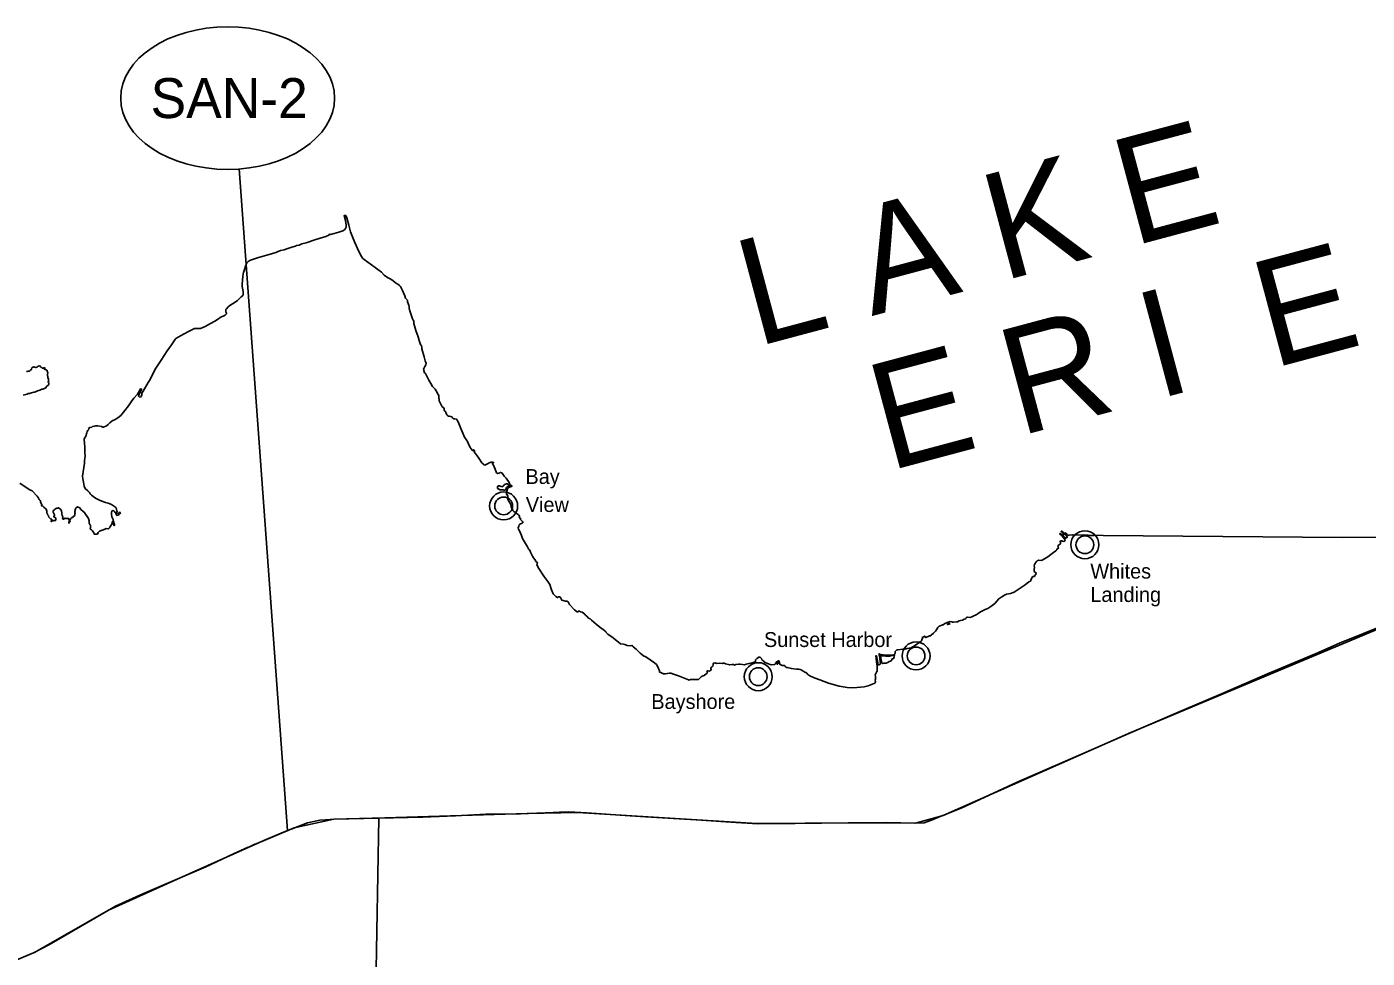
# Model space of a CAD drawing. Extents: x 0 to 798, y 0 to 440.
# Drawn here: x 446.4 to 540.4, y 256.2 to 321.5 of the extents above; entities that cross this region are included whole.
import ezdxf

# ---------------------------------------------------------------- set-up
doc = ezdxf.new("R2010")
doc.units = 0
for name, color, linetype in [('DV_X_Corp_Line', 7, 'Continuous'), ('GM_X_County', 7, 'Continuous'), ('GM_X_State_Route', 7, 'Continuous'), ('GM_X_US_Route', 7, 'Continuous'), ('RW_X_Esmt_U', 7, 'Continuous'), ('SH_Data', 7, 'Continuous'), ('SH_Text', 7, 'Continuous')]:
    doc.layers.add(name, color=color, linetype=linetype)

msp = doc.modelspace()

# ---------------------------------------------------------------- linework, layer by layer
at = {"layer": 'DV_X_Corp_Line'}
for centre, radius in [((479.809, 287.947), 0.982), ((479.809, 287.947), 0.623), ((520.571, 285.224), 0.982), ((520.571, 285.224), 0.623), ((508.733, 277.427), 0.982), ((508.733, 277.427), 0.623), ((497.666, 275.97), 0.982), ((497.666, 275.97), 0.623)]:
    msp.add_circle(centre, radius, dxfattribs=at)
at = {"layer": 'GM_X_County'}
for points in [[(445.874, 289.536), (446.384, 289.193), (446.572, 289.072), (446.735, 289), (447.1, 288.642), (447.177, 288.537), (447.234, 288.405), (447.28, 288.354), (447.306, 288.325), (447.345, 288.243), (447.322, 288.215), (447.365, 288.14), (447.425, 288.019), (447.396, 287.98), (447.409, 287.952), (447.497, 287.936), (447.569, 287.867), (447.718, 287.715), (447.767, 287.584), (447.777, 287.465), (447.772, 287.429), (447.816, 287.388), (447.847, 287.305), (447.891, 287.251), (447.919, 287.161), (448.063, 287.027), (448.123, 287.009), (448.125, 286.973), (448.097, 286.917), (448.079, 286.868), (448.084, 286.837), (448.112, 286.875), (448.189, 286.904), (448.22, 286.901), (448.262, 286.929), (448.316, 286.927), (448.354, 286.919), (448.388, 286.909), (448.38, 286.96), (448.411, 286.986), (448.406, 287.04), (448.408, 287.097), (448.38, 287.117), (448.339, 287.138), (448.295, 287.169), (448.262, 287.208), (448.264, 287.231), (448.28, 287.244), (448.316, 287.244), (448.326, 287.267), (448.316, 287.329), (448.285, 287.37), (448.256, 287.424), (448.226, 287.509), (448.223, 287.568), (448.244, 287.627), (448.287, 287.653), (448.305, 287.689), (448.372, 287.748), (448.475, 287.779), (448.514, 287.782), (448.547, 287.8), (448.586, 287.813), (448.671, 287.766), (448.751, 287.684), (448.792, 287.584), (448.833, 287.473), (448.82, 287.414), (448.815, 287.37), (448.841, 287.28), (448.885, 287.179), (448.893, 287.133), (448.875, 287.107), (448.877, 287.076), (448.89, 287.061), (448.898, 287.02), (448.916, 287.012), (448.952, 287.002), (448.983, 287.056), (449.034, 287.079), (449.096, 287.063), (449.122, 287.053), (449.178, 287.053), (449.305, 287.056), (449.32, 287.025), (449.33, 286.976), (449.346, 286.953), (449.354, 286.917), (449.343, 286.845), (449.323, 286.808), (449.305, 286.772), (449.307, 286.741), (449.338, 286.739), (449.346, 286.762), (449.346, 286.788), (449.372, 286.814), (449.392, 286.85), (449.413, 286.86), (449.402, 286.888), (449.382, 286.896), (449.382, 286.922), (449.384, 286.968), (449.387, 287.012), (449.446, 287.02), (449.462, 287.061), (449.469, 287.099), (449.524, 287.138), (449.572, 287.141), (449.59, 287.146), (449.611, 287.182), (449.655, 287.231), (449.681, 287.236), (449.712, 287.236), (449.719, 287.277), (449.737, 287.313), (449.742, 287.378), (449.771, 287.427), (449.748, 287.494), (449.742, 287.545), (449.771, 287.617), (449.76, 287.682), (449.79, 287.742), (449.812, 287.788), (449.831, 287.824), (449.923, 287.881), (449.969, 287.87), (450.083, 287.802), (450.151, 287.696), (450.297, 287.574), (450.43, 287.469), (450.465, 287.401), (450.555, 287.268), (450.685, 287.067), (450.731, 286.905), (450.736, 286.794), (450.75, 286.731), (450.785, 286.655), (450.834, 286.604), (450.828, 286.425), (450.823, 286.333), (450.904, 286.273), (450.967, 286.203), (451.062, 286.062), (451.094, 285.959), (451.322, 285.967), (451.376, 286.086), (451.474, 286.175), (451.644, 286.251), (451.753, 286.276), (451.837, 286.316), (451.932, 286.357), (452.105, 286.338), (452.162, 286.4), (452.192, 286.455), (452.238, 286.533), (452.292, 286.596), (452.333, 286.685), (452.352, 286.794), (452.376, 286.872), (452.42, 286.845), (452.444, 286.791), (452.447, 286.72), (452.447, 286.642), (452.468, 286.593), (452.479, 286.571), (452.498, 286.596), (452.536, 286.596), (452.517, 286.623), (452.517, 286.672), (452.504, 286.712), (452.479, 286.712), (452.468, 286.788), (452.447, 286.861), (452.42, 287), (452.341, 287.178), (452.319, 287.36), (452.317, 287.501), (452.352, 287.599), (452.417, 287.615), (452.485, 287.574), (452.561, 287.493), (452.604, 287.433), (452.647, 287.325), (452.707, 287.282), (452.818, 287.319), (452.883, 287.39), (452.927, 287.42), (452.935, 287.452), (452.902, 287.515), (452.853, 287.493), (452.815, 287.436), (452.745, 287.406), (452.699, 287.431), (452.669, 287.485), (452.683, 287.515), (452.71, 287.547), (452.688, 287.599), (452.656, 287.694), (452.639, 287.81), (452.515, 287.908), (452.455, 287.962), (452.317, 288.038), (452.075, 288.135), (451.883, 288.176), (451.636, 288.274), (451.474, 288.344), (451.178, 288.501), (451.005, 288.623), (450.915, 288.691), (450.823, 288.794), (450.755, 288.881), (450.652, 289.003), (450.473, 289.168), (450.389, 289.331), (450.335, 289.621), (450.308, 289.849), (450.278, 290.038), (450.365, 290.632), (450.424, 290.952), (450.424, 291.139), (450.435, 291.275), (450.452, 291.464), (450.441, 291.657), (450.427, 291.841), (450.43, 291.977), (450.449, 292.15), (450.419, 292.264), (450.419, 292.343), (450.405, 292.421), (450.392, 292.53), (450.397, 292.625), (450.422, 292.703), (450.481, 292.801), (450.525, 292.909), (450.544, 292.999), (450.579, 293.064), (450.595, 293.167), (450.652, 293.237), (450.709, 293.297), (450.704, 293.381), (450.782, 293.443), (450.929, 293.481), (450.983, 293.508), (451.094, 293.533), (451.208, 293.571), (451.343, 293.571), (451.609, 293.519), (451.701, 293.481), (451.753, 293.479), (451.959, 293.573), (452.065, 293.647), (452.184, 293.785), (452.36, 293.912), (452.555, 294.007), (452.745, 294.116), (452.959, 294.295), (453.249, 294.642), (453.49, 294.967), (453.691, 295.246), (453.867, 295.512), (454.141, 295.775), (454.263, 296.021), (454.301, 296.095), (454.325, 296.138), (454.38, 296.149), (454.413, 296.141), (454.404, 296.097), (454.336, 295.948), (454.222, 295.718), (454.198, 295.655), (454.247, 295.601), (454.331, 295.574), (454.404, 295.664), (454.426, 295.737), (454.442, 295.864), (454.534, 295.994), (454.881, 296.607), (455.009, 296.821), (455.095, 296.987), (455.413, 297.613), (455.784, 298.166), (456.21, 298.827), (456.508, 299.242), (456.741, 299.586), (456.825, 299.678), (457.147, 299.865), (457.4, 300.02), (457.747, 300.21), (457.947, 300.305), (458.123, 300.378), (458.321, 300.378), (458.56, 300.397), (458.882, 300.54), (459.24, 300.736), (459.544, 300.893), (459.807, 301.056), (459.918, 301.169), (460.064, 301.24), (460.143, 301.251), (460.273, 301.329), (460.365, 301.422), (460.371, 301.468), (460.327, 301.562), (460.325, 301.63), (460.338, 301.731), (460.384, 301.769), (460.479, 301.899), (460.615, 302.007), (460.989, 302.229), (461.143, 302.349), (461.317, 302.514), (461.409, 302.603), (461.501, 302.674), (461.534, 302.715), (461.539, 302.978), (461.479, 303.341), (461.479, 303.503), (461.517, 304.046), (461.545, 304.23), (461.577, 304.317), (461.637, 304.534), (461.707, 304.759), (461.794, 304.994), (461.9, 305.095), (462.065, 305.171), (462.61, 305.379), (463.377, 305.58), (463.824, 305.729), (464.163, 305.87), (464.415, 305.913), (464.616, 305.984), (464.958, 306.092), (465.207, 306.168), (465.291, 306.209), (465.478, 306.244), (465.668, 306.331), (465.95, 306.401), (466.557, 306.602), (466.95, 306.729), (467.343, 306.849), (467.552, 306.941), (467.563, 306.971), (467.62, 306.995), (467.668, 306.976), (467.915, 307.055), (468.249, 307.152), (468.528, 307.239), (468.639, 307.31), (468.728, 307.407), (468.772, 307.489), (468.769, 307.646), (468.718, 307.96), (468.62, 308.31), (468.742, 308.318), (468.812, 308.161), (468.943, 307.638), (469.081, 307.169), (469.352, 306.469), (469.458, 306.212), (469.626, 305.829), (469.837, 305.431), (469.905, 305.328), (470.024, 305.225), (470.797, 304.669), (470.989, 304.523), (471.236, 304.328), (471.431, 304.135), (471.672, 303.959), (471.86, 303.864), (472.036, 303.747), (472.231, 303.601), (472.38, 303.49), (472.51, 303.4), (472.57, 303.341), (472.708, 303.048), (472.787, 302.885), (472.871, 302.669), (472.93, 302.519), (472.974, 302.471), (473.031, 302.427), (473.063, 302.384), (473.071, 302.338), (473.058, 302.265), (473.15, 302.031), (473.188, 301.899), (473.188, 301.793), (473.25, 301.554), (473.426, 301.069), (473.459, 300.969), (473.508, 300.893), (473.51, 300.831), (473.51, 300.744), (473.654, 300.253), (473.811, 299.795), (473.887, 299.537), (473.985, 299.269), (474.053, 299.169), (474.08, 299.085), (474.072, 299.036), (474.072, 298.971), (474.232, 298.412), (474.313, 298.117), (474.373, 297.935), (474.362, 297.84), (474.291, 297.729), (474.196, 297.542), (474.261, 297.287), (474.321, 297.233), (474.557, 296.764), (474.695, 296.536), (474.828, 296.311), (474.996, 296.124), (475.148, 295.902), (475.164, 295.824), (475.218, 295.756), (475.262, 295.68), (475.262, 295.577), (475.256, 295.487), (475.278, 295.43), (475.281, 295.311), (475.338, 295.222), (475.495, 294.896), (475.609, 294.815), (475.647, 294.753), (475.644, 294.652), (475.685, 294.598), (475.75, 294.544), (475.763, 294.49), (475.836, 294.341), (475.891, 294.262), (475.931, 294.235), (475.956, 294.23), (475.999, 294.238), (476.097, 294.216), (476.17, 294.189), (476.243, 294.102), (476.314, 294.064), (476.376, 294.064), (476.514, 294.024), (476.625, 293.855), (476.804, 293.367), (476.956, 293.039), (477.07, 292.771), (477.181, 292.608), (477.295, 292.424), (477.346, 292.267), (477.487, 292.026), (477.506, 291.969), (477.615, 291.841), (477.666, 291.83), (477.685, 291.849), (477.685, 291.874), (477.696, 291.893), (477.72, 291.876), (477.764, 291.83), (477.764, 291.765), (477.742, 291.741), (477.962, 291.451), (478.078, 291.288), (478.287, 290.979), (478.442, 290.817), (478.498, 290.814), (478.729, 290.914), (478.802, 290.963), (478.938, 291.017), (479.008, 291.02), (479.103, 290.998), (479.092, 290.979), (479.005, 290.903), (479.081, 290.849), (479.217, 290.516), (479.314, 290.269), (479.382, 290.209), (479.472, 290.239), (479.596, 290.293), (479.659, 290.269), (479.713, 290.255), (479.854, 290.044), (479.976, 289.887), (480.19, 289.578), (480.204, 289.542), (480.233, 289.51), (480.244, 289.469), (480.196, 289.445), (480.122, 289.453), (480.06, 289.488), (480, 289.488), (479.881, 289.453), (479.84, 289.404), (479.797, 289.344), (479.724, 289.298), (479.672, 289.296), (479.52, 289.347), (479.472, 289.355), (479.431, 289.347), (479.385, 289.296), (479.371, 289.225), (479.382, 289.176), (479.439, 289.136), (479.542, 289.073), (479.702, 289.073), (479.781, 289.073), (479.846, 289.046), (479.884, 289.041), (479.96, 289.098), (480.017, 289.236), (480.106, 289.307), (480.217, 289.353), (480.301, 289.369), (480.38, 289.374), (480.388, 289.35), (480.372, 289.307), (480.288, 289.293), (480.163, 289.236), (480.071, 289.144), (480.027, 288.97), (479.995, 288.889), (480.014, 288.783), (480.044, 288.713), (480.098, 288.718), (480.074, 288.678), (480.103, 288.602), (480.114, 288.477), (480.111, 288.398), (480.233, 288.163), (480.309, 288.013), (480.342, 287.889), (480.456, 287.626), (480.545, 287.523), (480.608, 287.498), (480.686, 287.441), (480.822, 287.352), (480.873, 287.29), (480.917, 287.233), (480.911, 287.173), (480.9, 287.141), (480.922, 287.111), (480.971, 287.094), (481.001, 287.073), (481.001, 286.997), (481.044, 286.937), (481.131, 286.85), (481.166, 286.807), (481.158, 286.775), (481.104, 286.745), (480.955, 286.669), (480.9, 286.612), (480.868, 286.517), (480.835, 286.411), (480.849, 286.322), (480.93, 286.189), (481.06, 285.877), (481.131, 285.658), (481.48, 285.067), (481.578, 284.899), (481.646, 284.836), (481.673, 284.766), (481.695, 284.709), (481.757, 284.56), (481.825, 284.427), (481.895, 284.302), (481.99, 284.18), (482.077, 284.077), (482.09, 284.031), (482.126, 284.004), (482.164, 283.988), (482.172, 283.925), (482.134, 283.844), (482.234, 283.625), (482.624, 283.02), (482.912, 282.64), (483.047, 282.443), (483.168, 282.059), (483.283, 281.781), (483.469, 281.599), (483.592, 281.523), (483.668, 281.563), (483.755, 281.571), (483.767, 281.543), (483.814, 281.468), (483.89, 281.337), (484.144, 281.257), (484.251, 281.277), (484.334, 281.214), (484.438, 281.031), (484.779, 280.65), (484.981, 280.499), (485.04, 280.559), (485.119, 280.559), (485.207, 280.514), (485.305, 280.493), (485.499, 280.36), (485.554, 280.288), (485.635, 280.206), (485.764, 280.077), (485.882, 280.018), (485.963, 279.944), (486.291, 279.654), (486.676, 279.348), (486.757, 279.31), (486.925, 279.158), (487, 279.097), (487.004, 279.059), (487.117, 278.95), (487.481, 278.69), (487.651, 278.557), (487.866, 278.387), (488.016, 278.283), (488.226, 278.24), (488.312, 278.219), (488.466, 278.147), (488.676, 278.131), (488.796, 278.147), (488.855, 278.131), (488.884, 278.086), (488.896, 278.072), (489.097, 277.909), (489.391, 277.626), (489.627, 277.443), (489.772, 277.355), (490.082, 277.149), (490.396, 276.936), (490.518, 276.823), (490.634, 276.665), (490.735, 276.389), (490.738, 276.291), (490.831, 276.262), (491.025, 276.167), (491.152, 276.162), (491.292, 276.196), (491.432, 276.212), (491.534, 276.217), (491.729, 276.156), (491.935, 276.072), (492.061, 276.033), (492.19, 275.986), (492.414, 275.884), (492.763, 275.755), (492.831, 275.735), (492.86, 275.76), (492.908, 275.791), (492.971, 275.782), (493.01, 275.771), (493.154, 275.771), (493.234, 275.764), (493.388, 275.766), (493.469, 275.782), (493.569, 275.861), (493.666, 275.972), (493.734, 276.013), (493.883, 276.065), (494.019, 276.167), (494.069, 276.203), (494.096, 276.248), (494.089, 276.285), (494.063, 276.313), (494.096, 276.377), (494.139, 276.386), (494.267, 276.356), (494.324, 276.411), (494.361, 276.466), (494.347, 276.563), (494.376, 276.649), (494.422, 276.676), (494.471, 276.717), (494.494, 276.792), (494.514, 276.9), (494.544, 276.927), (494.634, 276.939), (494.738, 276.907), (494.962, 276.914), (495.153, 276.9), (495.202, 276.916), (495.279, 276.911), (495.374, 276.873), (495.571, 276.83), (495.666, 276.792), (495.822, 276.825), (495.922, 276.816), (495.997, 276.789), (496.094, 276.814), (496.279, 276.844), (496.402, 276.848), (496.571, 276.83), (496.691, 276.81), (496.811, 276.853), (497.008, 276.891), (497.164, 276.923), (497.381, 277), (497.463, 277.022), (497.461, 277.068), (497.463, 277.151), (497.508, 277.194), (497.558, 277.235), (497.651, 277.298), (497.68, 277.337), (497.732, 277.346), (497.807, 277.328), (497.893, 277.237), (497.927, 277.158), (497.99, 277.115), (498.02, 277.102), (498.042, 277.072), (498.058, 277.029), (498.151, 276.973), (498.323, 276.891), (498.563, 276.805), (498.8, 276.828), (498.873, 276.88), (498.913, 276.952), (498.931, 277.009), (498.945, 277.018), (498.965, 277.004), (498.961, 276.952), (498.961, 276.868), (498.993, 276.841), (499.026, 276.841), (499.081, 276.923), (499.083, 276.991), (499.076, 277.022), (499.038, 277.031), (499.04, 277.072), (499.076, 277.088), (499.115, 277.081), (499.149, 276.975), (499.16, 276.887), (499.198, 276.828), (499.334, 276.764), (499.486, 276.746), (499.547, 276.699), (499.565, 276.653), (499.622, 276.624), (499.703, 276.624), (499.99, 276.536), (500.16, 276.524), (500.348, 276.502), (500.513, 276.497), (500.595, 276.47), (500.672, 276.452), (500.816, 276.353), (500.968, 276.276), (501.025, 276.264), (501.068, 276.224), (501.131, 276.126), (501.28, 276.04), (501.534, 275.923), (501.647, 275.867), (501.979, 275.742), (502.602, 275.511), (503.346, 275.316), (503.898, 275.214), (504.186, 275.194), (504.584, 275.201), (505.082, 275.253), (505.38, 275.323), (505.733, 275.472), (505.835, 275.524), (505.869, 275.57), (505.887, 275.631), (505.874, 275.717), (505.858, 275.751), (505.881, 275.755), (505.892, 275.769), (505.894, 275.882), (505.876, 276.011), (505.869, 276.09), (505.926, 276.233), (505.98, 276.325), (506.005, 276.353), (506.012, 276.481), (506.005, 276.543), (505.994, 276.699), (505.964, 277.004), (505.937, 277.278), (505.908, 277.432), (505.957, 277.439), (506, 277.199), (506.048, 276.952), (506.05, 276.868), (506.071, 276.792), (506.154, 276.794), (506.188, 276.844), (506.231, 276.862), (506.172, 277.434), (506.136, 277.493), (506.136, 277.545), (506.168, 277.593), (506.193, 277.579), (506.227, 277.531), (506.62, 277.486), (507.125, 277.513), (507.168, 277.484), (507.078, 277.445), (506.881, 277.409), (506.607, 277.4), (506.365, 277.427), (506.249, 277.43), (506.256, 277.273), (506.274, 277.147), (506.29, 277.117), (506.317, 277.079), (506.322, 276.988), (506.31, 276.959), (506.374, 276.9), (506.417, 276.896), (506.449, 276.925), (506.55, 276.925), (506.641, 276.93), (506.747, 276.968), (506.847, 277.027), (506.944, 277.056), (507.016, 277.104), (507.046, 277.163), (507.039, 277.215), (507.1, 277.224), (507.184, 277.258), (507.155, 277.283), (507.182, 277.326), (507.204, 277.371), (507.188, 277.43), (507.225, 277.468), (507.211, 277.545), (507.256, 277.604), (507.274, 277.74), (507.336, 277.812), (507.392, 277.857), (507.446, 277.864), (507.804, 277.896), (507.96, 277.925), (507.958, 277.905), (508.114, 277.936), (508.247, 277.97), (508.288, 277.966), (508.306, 277.952), (508.612, 278.136), (509.094, 278.452), (509.132, 278.514), (509.137, 278.59), (509.193, 278.647), (509.2, 278.67), (509.168, 278.719), (509.336, 278.814), (509.386, 278.726), (509.407, 278.721), (509.675, 278.842), (509.69, 278.823), (509.826, 278.903), (509.965, 279.025), (510.089, 279.174), (510.171, 279.26), (510.25, 279.412), (510.354, 279.509), (510.415, 279.548), (510.528, 279.577), (510.589, 279.616), (510.637, 279.609), (510.759, 279.699), (510.872, 279.758), (510.954, 279.801), (510.967, 279.785), (510.979, 279.706), (510.927, 279.674), (510.936, 279.636), (510.967, 279.638), (511.105, 279.674), (511.085, 279.711), (511.058, 279.715), (511.028, 279.715), (511.006, 279.74), (511.008, 279.803), (511.117, 279.842), (511.234, 279.817), (511.282, 279.797), (511.35, 279.797), (511.569, 279.81), (511.637, 279.812), (511.766, 279.878), (511.852, 279.903), (511.995, 279.946), (512.097, 279.998), (512.232, 280.03), (512.257, 280.111), (512.332, 280.156), (512.526, 280.131), (512.633, 280.159), (512.791, 280.236), (512.936, 280.301), (513.079, 280.394), (513.249, 280.52), (513.384, 280.581), (513.585, 280.686), (513.76, 280.758), (513.905, 280.847), (514.066, 280.952), (514.256, 281.103), (514.398, 281.274), (514.531, 281.439), (514.758, 281.577), (514.932, 281.686), (515.072, 281.763), (515.217, 281.779), (515.357, 281.795), (515.611, 281.896), (515.821, 282.03), (516.17, 282.263), (516.325, 282.369), (516.496, 282.509), (516.631, 282.615), (516.753, 282.679), (516.785, 282.711), (516.781, 282.774), (516.903, 282.969), (516.95, 283.017), (516.998, 282.994), (517.029, 283.005), (517.113, 283.132), (517.143, 283.139), (517.149, 283.254), (517.12, 283.259), (517.068, 283.308), (517.019, 283.377), (517.003, 283.483), (517.025, 283.553), (517.043, 283.591), (517.036, 283.661), (517.009, 283.745), (517.029, 283.842), (517.154, 284.033), (517.226, 284.103), (517.351, 284.134), (517.53, 284.13), (517.74, 284.229), (517.969, 284.386), (518.179, 284.539), (518.362, 284.682), (518.534, 284.8), (518.6, 284.874), (518.604, 284.917), (518.625, 284.933), (518.663, 284.933), (518.697, 284.972), (518.711, 285.008), (518.686, 285.112), (518.69, 285.168), (518.799, 285.245), (518.831, 285.261), (518.865, 285.291), (518.871, 285.334), (518.853, 285.383), (518.831, 285.44), (518.847, 285.476), (518.903, 285.488), (518.955, 285.501), (519.012, 285.483), (519.086, 285.454), (519.111, 285.454), (519.145, 285.475), (519.181, 285.557), (519.086, 285.685), (518.981, 285.82), (518.88, 285.91), (518.817, 285.957), (518.814, 285.989), (518.828, 286.016), (518.855, 286.016), (518.967, 285.93), (519.012, 285.924), (519.048, 285.903), (519.066, 285.883), (519.075, 285.825), (519.129, 285.766), (519.183, 285.697), (519.235, 285.676), (519.329, 285.755), (519.266, 285.881), (519.192, 285.953), (519.161, 285.964), (519.109, 285.969), (519.048, 286.018), (518.943, 286.126), (518.909, 286.142), (518.911, 286.169), (518.954, 286.178), (519.028, 286.124), (519.12, 286.043), (519.21, 286.056), (519.246, 286.032), (519.376, 285.863), (519.446, 285.901), (519.687, 285.912), (519.743, 285.901), (519.828, 285.901), (520.491, 285.917), (520.8, 285.896), (520.943, 285.883), (520.978, 285.878), (521.061, 285.868), (521.13, 285.865), (521.165, 285.867), (521.206, 285.875), (521.245, 285.889), (521.264, 285.897), (521.853, 285.883), (538.638, 285.734), (556.572, 285.782)], [(446.351, 297.383), (446.4, 297.373), (446.464, 297.398), (446.51, 297.398), (446.549, 297.398), (446.585, 297.424), (446.606, 297.432), (446.624, 297.465), (446.631, 297.491), (446.66, 297.506), (446.673, 297.483), (446.691, 297.532), (446.722, 297.625), (446.765, 297.666), (446.819, 297.687), (446.85, 297.687), (446.889, 297.707), (446.915, 297.684), (446.992, 297.653), (447.113, 297.697), (447.162, 297.741), (447.237, 297.764), (447.306, 297.749), (447.329, 297.71), (447.365, 297.661), (447.414, 297.658), (447.443, 297.622), (447.466, 297.599), (447.52, 297.604), (447.566, 297.62), (447.6, 297.648), (447.633, 297.609), (447.623, 297.571), (447.597, 297.543), (447.646, 297.514), (447.726, 297.499), (447.752, 297.481), (447.801, 297.455), (447.793, 297.396), (447.78, 297.38), (447.819, 297.347), (447.844, 297.331), (447.816, 297.13), (447.811, 297.071), (447.847, 297.015), (447.837, 296.924), (447.888, 296.852), (447.888, 296.747), (447.898, 296.664), (447.852, 296.631), (447.886, 296.603), (447.911, 296.564), (447.911, 296.476), (447.896, 296.435), (447.731, 296.296), (447.692, 296.234), (447.62, 296.18), (447.548, 296.157), (447.484, 296.139), (447.414, 296.131), (447.291, 296.056), (447.201, 296.044), (447.123, 296.01), (447.061, 295.992), (446.982, 295.943), (446.92, 295.933), (446.855, 295.93), (446.696, 295.879), (446.567, 295.835), (446.474, 295.84), (446.389, 295.784), (446.106, 295.719)]]:
    msp.add_lwpolyline(points, dxfattribs=at)
at = {"layer": 'GM_X_State_Route'}
msp.add_lwpolyline([(469.488, 195.343), (469.722, 206.488), (469.906, 206.741), (469.984, 206.905), (470.105, 213.119), (470.31, 219.731), (470.468, 230.182), (470.519, 233.299), (470.702, 246.178), (471.047, 266.057)], dxfattribs=at)
at = {"layer": 'GM_X_US_Route'}
for points in [[(516.739, 268.965), (516.74, 268.965), (520.277, 270.512), (523.664, 271.997), (525.17, 272.645), (527.506, 273.651), (530.157, 274.761), (533.373, 276.17), (536.78, 277.606), (538.433, 278.327), (546.836, 281.711), (565.775, 289.63)], [(483.768, 266.474), (484.374, 266.497), (485.653, 266.415), (487.981, 266.264), (489.764, 266.142), (493.309, 265.925), (496.098, 265.735), (497.664, 265.66), (500.246, 265.669), (503.973, 265.717), (506.672, 265.743), (508.643, 265.692), (509.3, 265.713), (509.816, 265.905), (510.254, 266.084), (511.885, 266.752), (515.818, 268.562), (516.739, 268.965)], [(467.383, 265.93), (467.906, 265.969), (471.047, 266.057), (474.147, 266.108), (476.434, 266.224), (477.73, 266.285), (478.555, 266.324), (480.998, 266.354), (483.28, 266.455), (483.729, 266.472), (483.768, 266.474)], [(462.453, 264.253), (463.308, 264.629), (464.48, 265.117), (466.045, 265.724), (466.928, 265.897), (467.322, 265.926), (467.383, 265.93)], [(461.979, 264.044), (462.367, 264.215), (462.453, 264.253)], [(444.366, 255.572), (444.489, 255.618), (446.841, 256.594), (447.964, 257.197), (452.579, 259.871), (454.511, 260.742), (458.933, 262.646), (460.862, 263.553), (461.896, 264.008), (461.979, 264.044)]]:
    msp.add_lwpolyline(points, dxfattribs=at)
at = {"layer": 'SH_Data'}
msp.add_line((461.27, 311.576), (464.657, 265.173), dxfattribs=at)
msp.add_ellipse((460.454, 316.547), major_axis=(7.5, 0), ratio=0.666667, dxfattribs=at)
at = {"layer": 'SH_Text'}
msp.add_lwpolyline([(446.901, 256.627), (452.098, 259.592), (456.653, 261.664), (462.561, 264.3), (465.11, 265.361), (467.906, 265.969), (471.469, 266.064), (481.455, 266.375), (485.005, 266.456), (491.844, 266.015), (497.558, 265.665), (504.325, 265.72), (508.682, 265.693), (510.644, 266.244), (523.798, 272.054), (556.954, 285.941)], dxfattribs=at)

# ---------------------------------------------------------------- texts
at = {"layer": 'DV_X_Corp_Line'}
for s, height, p in [('Bay', 1.0417, (481.339, 289.486)), ('View', 1.0417, (481.366, 287.522)), ('Whites', 1.0417, (520.956, 282.849)), ('Landing', 1.0417, (520.956, 281.21)), ('Sunset Harbor', 1.04167, (498.065, 278.053)), ('Bayshore', 1.0417, (490.167, 273.708))]:
    msp.add_text(s, height=height, rotation=0.00001, dxfattribs=at).set_placement(p)
at = {"layer": 'RW_X_Esmt_U'}
for s, rotation, p in [('L A K E', 14.97219, (497.537, 299.092)), ('E R I  E', 14.97218, (506.808, 290.378))]:
    msp.add_text(s, height=7.5, rotation=rotation, dxfattribs=at).set_placement(p)
at = {"layer": 'SH_Data'}
msp.add_text('SAN-2', height=2.8, dxfattribs=at).set_placement((455.048, 315.147))

doc.saveas('drawing.dxf')
